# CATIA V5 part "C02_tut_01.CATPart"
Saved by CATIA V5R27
Part number: Part1
Bounding box of the stored display mesh (mm): x 0 to 0, y 0 to 120, z 0 to 59.999
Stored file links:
  E:\_Deepak\2017_Deepak\CATIA\Resources\Tutorial Files\Tutorials\c02_catia_v5_6r2016_tut\C02_tut_01.CATPart
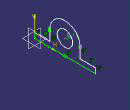
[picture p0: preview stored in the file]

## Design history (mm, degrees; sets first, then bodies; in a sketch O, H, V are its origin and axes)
Body1 (main body)
  Sketch1 on yz-plane, origin (0, 0, 0), H (0, 1, 0), V (0, 0, 1)
    line L1 (0, 0) -> (120, 0)
    line L2 (120, 0) -> (120, 10)
    line L3 (120, 10) -> (90, 10)
    line L4 (90, 10) -> (90, 30)
    arc A1 centre (60, 30) radius 30 from (90, 30) to (30, 30) ccw
    line L5 (30, 30) -> (30, 10)
    point P7 (30, 10)
    line L6 (30, 10) -> (0, 10)
    line L7 (0, 10) -> (0, 0)
    circle A2 centre (60, 30) radius 15
    radius A2 = 15
    horizontal: L1 H, L3 H, L6 H
    vertical: L2 V, L4 V, L7 V
    tangency: A1 L1, A1 L4, L5 A1
    coincidence: P7 L3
